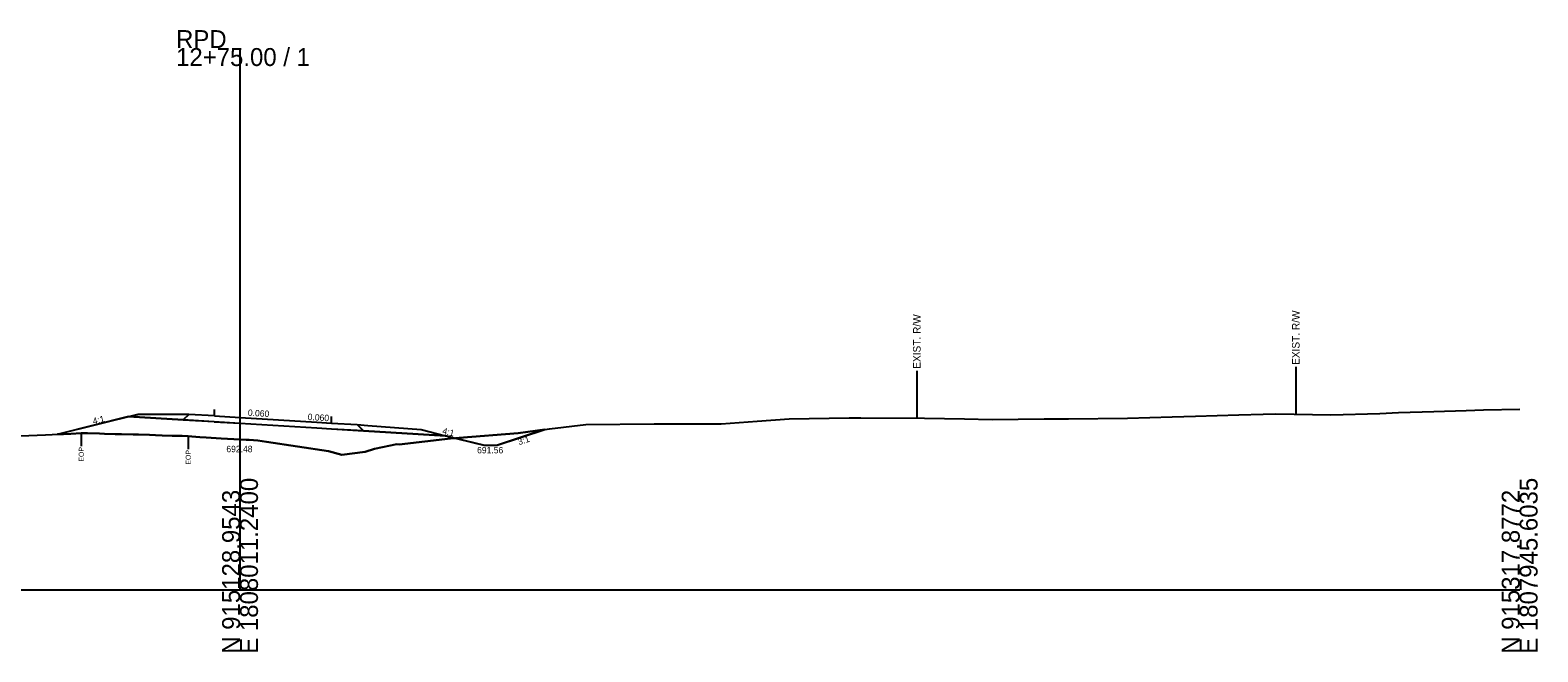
# Model space of a CAD drawing. Extents: x -26 to 403, y -10 to 8517.
# Drawn here: x 167.2 to 402.8, y 5490.3 to 5587.4 of the extents above; entities that cross this region are included whole.
import ezdxf

# ---------------------------------------------------------------- set-up
doc = ezdxf.new("R2010")
doc.units = 0
for name, color, linetype in [('Exist Cross Section Cell', 7, 'Continuous'), ('Exist XS Center Line Elevation Label', 7, 'Continuous'), ('Exist XS Ground Line', 7, 'Continuous'), ('Old_Level_10', 7, 'Continuous'), ('Prop XS Ditch Slope Text', 7, 'Continuous'), ('Prop XS Ditch Standard Text', 7, 'Continuous'), ('Prop XS Earthwork Shape', 7, 'Continuous'), ('Prop XS EOT Tick Mark', 7, 'Continuous'), ('Prop XS Finish Grade', 7, 'Continuous'), ('Prop XS Finish Grade Earthwork', 7, 'Continuous'), ('Prop XS Finish Grade Paved Shoulder', 7, 'Continuous'), ('Prop XS Finish Grade Pavement', 7, 'Continuous'), ('Prop XS Hydro Fill Slope Data', 7, 'Continuous'), ('Prop XS Pvmt Edge Slope', 7, 'Continuous'), ('Prop XS SE Text', 7, 'Continuous'), ('Prop XS Side Slope Text', 7, 'Continuous'), ('Prop XS Subgrade Earthwork', 7, 'Continuous')]:
    doc.layers.add(name, color=color, linetype=linetype)

msp = doc.modelspace()

# ---------------------------------------------------------------- linework, layer by layer
at = {"layer": 'Exist Cross Section Cell'}
for p, q in [((200, 5500), (200, 5584.59)), ((0, 5500), (200, 5500)), ((200, 5500), (400, 5500))]:
    msp.add_line(p, q, dxfattribs=at)
at = {"layer": 'Exist XS Ground Line'}
msp.add_lwpolyline([(164.35, 5523.98), (168.27, 5524.15), (169.57, 5524.21), (171.68, 5524.29), (172.4, 5524.3), (173.55, 5524.33), (175.19, 5524.45), (175.68, 5524.44), (176.18, 5524.43), (178.01, 5524.39), (178.82, 5524.37), (180.47, 5524.32), (181.47, 5524.3), (183.29, 5524.26), (184.13, 5524.24), (185.87, 5524.18), (186.77, 5524.15), (187.82, 5524.11), (189.41, 5524.06), (189.81, 5524.05), (190.94, 5524.02), (191.9, 5523.98), (192.48, 5523.93), (193.73, 5523.83), (194.71, 5523.78), (196.29, 5523.68), (197.06, 5523.63), (200, 5523.48), (200.95, 5523.43), (201.44, 5523.41), (202.76, 5523.33), (204.11, 5523.11), (213.84, 5521.63), (215.93, 5521.05), (219.54, 5521.54), (221.04, 5521.99), (224.52, 5522.74), (224.86, 5522.68), (232.87, 5523.63), (234.25, 5523.73), (243.45, 5524.47), (248.35, 5525.13), (254.04, 5525.83), (264.72, 5525.91), (275.21, 5525.89), (280.8, 5526.34), (285.8, 5526.68), (295.19, 5526.84), (296.38, 5526.85), (297.02, 5526.83), (306.97, 5526.81), (313.24, 5526.71), (317.56, 5526.6), (325.66, 5526.67), (328.14, 5526.71), (329.46, 5526.71), (338.73, 5526.81), (345.69, 5527.01), (349.32, 5527.09), (356.13, 5527.33), (359.9, 5527.44), (361.91, 5527.46), (370.49, 5527.31), (378.13, 5527.53), (381.07, 5527.67), (386.6, 5527.84), (391.66, 5528.01), (394.35, 5528.09), (400, 5528.2)], dxfattribs=at)
at = {"layer": 'Old_Level_10'}
for p, q in [((305.78, 5534.21), (305.78, 5526.81)), ((365.01, 5534.81), (365.01, 5527.4)), ((175.19, 5524.45), (175.19, 5522.4)), ((191.9, 5523.98), (191.9, 5521.93))]:
    msp.add_line(p, q, dxfattribs=at)
at = {"layer": 'Prop XS Earthwork Shape'}
for points in [[(199.98, 5526.01), (211.98, 5525.29), (214.29, 5525.15), (219.29, 5524.86), (232.09, 5524.09), (233.68, 5523.69), (232.87, 5523.63), (224.86, 5522.68), (224.52, 5522.74), (221.04, 5521.99), (219.54, 5521.54), (215.93, 5521.05), (213.84, 5521.63), (204.11, 5523.11), (202.76, 5523.33), (201.44, 5523.41), (200.95, 5523.43), (200, 5523.48), (197.06, 5523.63), (196.29, 5523.68), (194.71, 5523.78), (193.73, 5523.83), (192.48, 5523.93), (191.9, 5523.98), (190.94, 5524.02), (189.81, 5524.05), (189.41, 5524.06), (187.82, 5524.11), (186.77, 5524.15), (185.87, 5524.18), (184.13, 5524.24), (183.29, 5524.26), (181.47, 5524.3), (180.47, 5524.32), (178.82, 5524.37), (178.01, 5524.39), (176.18, 5524.43), (175.68, 5524.44), (175.19, 5524.45), (173.55, 5524.33), (172.4, 5524.3), (171.68, 5524.29), (171.48, 5524.28), (182.59, 5527.06), (191.13, 5526.54), (195.98, 5526.25)], [(240.2, 5522.56), (247.62, 5525.03), (243.45, 5524.47), (234.25, 5523.73), (233.68, 5523.69), (238.2, 5522.56)]]:
    msp.add_lwpolyline(points, close=True, dxfattribs=at)
at = {"layer": 'Prop XS EOT Tick Mark'}
for p, q in [((196, 5527.14), (196, 5528.14)), ((214.31, 5526.04), (214.31, 5527.04))]:
    msp.add_line(p, q, dxfattribs=at)
at = {"layer": 'Prop XS Finish Grade'}
for p, q in [((182.59, 5527.03), (184, 5527.38)), ((190.43, 5527.38), (184, 5527.38)), ((192, 5527.38), (190.43, 5527.38)), ((218.31, 5525.8), (219.95, 5525.67)), ((219.95, 5525.67), (228.31, 5525)), ((228.31, 5525), (228.31, 5525)), ((228.31, 5525), (232.09, 5524.06))]:
    msp.add_line(p, q, dxfattribs=at)
at = {"layer": 'Prop XS Finish Grade Earthwork'}
for p, q in [((182.59, 5527.03), (171.61, 5524.29)), ((232.09, 5524.06), (238.09, 5522.56)), ((240.1, 5522.56), (247.44, 5525.01)), ((238.09, 5522.56), (240.1, 5522.56))]:
    msp.add_line(p, q, dxfattribs=at)
at = {"layer": 'Prop XS Finish Grade Paved Shoulder'}
for p, q in [((196, 5527.14), (192, 5527.38)), ((214.31, 5526.04), (218.31, 5525.8))]:
    msp.add_line(p, q, dxfattribs=at)
at = {"layer": 'Prop XS Finish Grade Pavement'}
for p, q in [((196, 5527.14), (200, 5526.9)), ((200, 5526.9), (212, 5526.18)), ((212, 5526.18), (214.31, 5526.04))]:
    msp.add_line(p, q, dxfattribs=at)
at = {"layer": 'Prop XS Hydro Fill Slope Data'}
msp.add_line((184, 5527.38), (171.61, 5524.29), dxfattribs=at)
at = {"layer": 'Prop XS Pvmt Edge Slope'}
for p, q in [((192, 5527.38), (191.13, 5526.52)), ((218.31, 5525.8), (219.29, 5524.83))]:
    msp.add_line(p, q, dxfattribs=at)
at = {"layer": 'Prop XS Subgrade Earthwork'}
for p, q in [((191.13, 5526.52), (182.59, 5527.03)), ((195.98, 5526.23), (191.13, 5526.52)), ((195.98, 5526.23), (199.98, 5525.99)), ((199.98, 5525.99), (211.98, 5525.27)), ((211.98, 5525.27), (214.29, 5525.13)), ((214.29, 5525.13), (219.29, 5524.83)), ((219.29, 5524.83), (232.09, 5524.06))]:
    msp.add_line(p, q, dxfattribs=at)

# ---------------------------------------------------------------- texts
at = {"layer": 'Exist Cross Section Cell'}
for s, p in [('RPD', (190, 5584.59)), ('12+75.00 / 1', (190, 5581.79))]:
    msp.add_text(s, height=2.8, dxfattribs=at).set_placement(p)
for s, p in [('E 1808011.2400', (202.8, 5490)), ('E 1807945.6035', (402.8, 5490)), ('N 915128.9543', (200, 5490)), ('N 915317.8772', (400, 5490))]:
    msp.add_text(s, height=2.8, rotation=90, dxfattribs=at).set_placement(p)
at = {"layer": 'Exist XS Center Line Elevation Label'}
msp.add_text('692.48', height=1, dxfattribs=at).set_placement((197.86, 5521.48))
at = {"layer": 'Old_Level_10'}
for s, height, rotation, p in [('EXIST. R/W', 1.181, 90, (306.37, 5534.51)), ('EXIST. R/W', 1.181, 90, (365.6, 5535.11)), ('3:1', 1, 18.4349, (243.6, 5522.57)), ('EOP', 0.787, 90, (175.58, 5520)), ('EOP', 0.787, 90, (192.3, 5519.53))]:
    msp.add_text(s, height=height, rotation=rotation, dxfattribs=at).set_placement(p)
at = {"layer": 'Prop XS Ditch Slope Text'}
msp.add_text('4:1', height=1, rotation=345.9638, dxfattribs=at).set_placement((231.55, 5524.38))
at = {"layer": 'Prop XS Ditch Standard Text'}
msp.add_text('691.56', height=1, dxfattribs=at).set_placement((237.05, 5521.3))
at = {"layer": 'Prop XS SE Text'}
for p in [(201.2, 5527.17), (210.55, 5526.51)]:
    msp.add_text('0.060', height=1, rotation=356.5664, dxfattribs=at).set_placement(p)
at = {"layer": 'Prop XS Side Slope Text'}
msp.add_text('4:1', height=1, rotation=14.0362, dxfattribs=at).set_placement((177.11, 5525.81))

doc.saveas('drawing.dxf')
